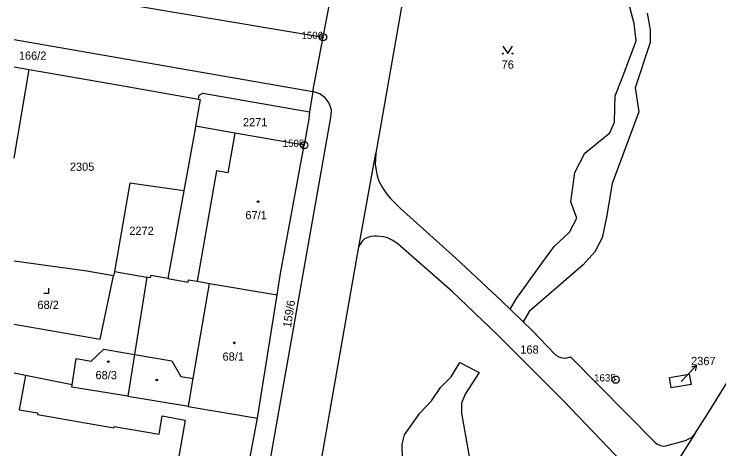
# Model space of a CAD drawing. Extents: x -866441 to -866144, y -1037389 to -1036968.
# Drawn here: x -866440.8 to -866295.1, y -1037160.7 to -1037070.9 of the extents above; entities that cross this region are included whole.
import ezdxf

# ---------------------------------------------------------------- set-up
doc = ezdxf.new("R2010")
doc.units = 0
for name, color, linetype in [('Hranice parcel', 7, 'Continuous'), ('Parcelní čísla', 7, 'Continuous'), ('Pop  PČ popisy', 7, 'Continuous'), ('Vnitřní kresba', 7, 'Continuous'), ('Značky bodu BP', 7, 'Continuous'), ('Značky budov', 7, 'Continuous'), ('Značky kultur', 7, 'Continuous')]:
    doc.layers.add(name, color=color, linetype=linetype)

msp = doc.modelspace()

# ---------------------------------------------------------------- linework, layer by layer
at = {"layer": 'Hranice parcel'}
for p, q in [((-866350.11, -1037008.35), (-866366.04, -1037099.65)), ((-866416.74, -1037068.97), (-866376.95, -1037075.67)), ((-866379.07, -1037086.89), (-866376.95, -1037075.67)), ((-866379.07, -1037086.89), (-866379.72, -1037091.09)), ((-866402.67, -1037088.49), (-866402.52, -1037087.66)), ((-866369.53, -1037118.99), (-866366.04, -1037099.65)), ((-866366.04, -1037099.65), (-866366.15, -1037102)), ((-866405.68, -1037107.4), (-866409.04, -1037125.54)), ((-866420.06, -1037124.1), (-866420.22, -1037124.95)), ((-866420.06, -1037124.1), (-866413.33, -1037125.28)), ((-866390.49, -1037154.39), (-866386.41, -1037128.93)), ((-866338.3, -1037131.85), (-866336.98, -1037129.68)), ((-866340, -1037130.19), (-866338.3, -1037131.85)), ((-866338.3, -1037131.85), (-866335.57, -1037134.5)), ((-866334.34, -1037132.32), (-866335.57, -1037134.5)), ((-866335.57, -1037134.5), (-866333.81, -1037136.22)), ((-866333.81, -1037136.22), (-866328.88, -1037141.28)), ((-866325.79, -1037141.71), (-866308.39, -1037159.36)), ((-866394.75, -1037177.03), (-866390.49, -1037154.39)), ((-866300.13, -1037157.61), (-866312.39, -1037176.98))]:
    msp.add_line(p, q, dxfattribs=at)
for points in [[(-866376.95, -1037075.67), (-866375.14, -1037066.22), (-866374.99, -1037066.24), (-866374.87, -1037065.62), (-866375.02, -1037065.59), (-866374.54, -1037063.06), (-866374.44, -1037063.08), (-866372.61, -1037053.54)], [(-866300.13, -1037157.61), (-866297.32, -1037153.2), (-866289.02, -1037139.82), (-866270.86, -1037110.87), (-866241.88, -1037065.54), (-866239.67, -1037062), (-866244.58, -1037059.28), (-866243.12, -1037056.62)], [(-866336.98, -1037129.68), (-866331.67, -1037122.27), (-866329.2, -1037118.89), (-866326.01, -1037115.95), (-866324.53, -1037113.03), (-866325.73, -1037109.68), (-866324.88, -1037103.62), (-866322.83, -1037099.61), (-866317.68, -1037095.43), (-866316.72, -1037093.21), (-866316.64, -1037090.36), (-866316.57, -1037087.76), (-866314.97, -1037083.76), (-866312.25, -1037076.44), (-866312.63, -1037072.83), (-866314.11, -1037067.33)], [(-866310, -1037070.73), (-866309.37, -1037074.15), (-866309.33, -1037076.74), (-866312.43, -1037086.11), (-866311.68, -1037091.11), (-866317.18, -1037105.91), (-866318.35, -1037112.87), (-866319.3, -1037117.13), (-866320.8, -1037120.02), (-866323.21, -1037122.72), (-866334.34, -1037132.32)], [(-866440.78, -1037076.16), (-866379.07, -1037086.89)], [(-866440.78, -1037081.77), (-866438.83, -1037082.11), (-866437.65, -1037082.32)], [(-866440.78, -1037100.69), (-866439.18, -1037091.3), (-866437.65, -1037082.32)], [(-866437.65, -1037082.32), (-866419.02, -1037085.56), (-866402.67, -1037088.49)], [(-866430.07, -1037388.86), (-866412.87, -1037304.8), (-866375.25, -1037091.87), (-866375.18, -1037090.66), (-866375.67, -1037089.29), (-866376.51, -1037088.18), (-866377.58, -1037087.37), (-866379.07, -1037086.89)], [(-866402.52, -1037087.66), (-866401.75, -1037087.22), (-866379.72, -1037091.09)], [(-866402.67, -1037088.49), (-866402.3, -1037088.56), (-866403.28, -1037094.08)], [(-866379.72, -1037091.09), (-866379.88, -1037092.56), (-866380.82, -1037097.97)], [(-866403.28, -1037094.08), (-866403.37, -1037094.6), (-866405.68, -1037107.4)], [(-866380.82, -1037097.97), (-866395.17, -1037095.52), (-866403.28, -1037094.08)], [(-866386.41, -1037128.93), (-866385.72, -1037124.52), (-866380.82, -1037097.97)], [(-866366.15, -1037102), (-866366, -1037103.14), (-866365.99, -1037103.18), (-866365.74, -1037104.3), (-866365.39, -1037105.4), (-866364.8, -1037106.51), (-866364.48, -1037107.04), (-866363.76, -1037108.08), (-866362.96, -1037109.05)], [(-866405.68, -1037107.4), (-866416.87, -1037105.86), (-866420.06, -1037124.1)], [(-866362.96, -1037109.05), (-866360.97, -1037111.04), (-866349.52, -1037121.34), (-866340, -1037130.19)], [(-866362.5, -1037117.65), (-866363.24, -1037117.3), (-866363.63, -1037117.15), (-866364.42, -1037116.94), (-866365.23, -1037116.83), (-866365.93, -1037116.77), (-866366.33, -1037116.78), (-866367.04, -1037116.88), (-866367.71, -1037117.07), (-866368.36, -1037117.36), (-866368.8, -1037117.76), (-866368.96, -1037117.95), (-866369.29, -1037118.45), (-866369.53, -1037118.99)], [(-866313.18, -1037165.84), (-866315.06, -1037163.56), (-866327.2, -1037150.88), (-866340.96, -1037137.11), (-866350.28, -1037128.19), (-866361.44, -1037118.43), (-866362.5, -1037117.65)], [(-866384.32, -1037301.69), (-866385.21, -1037304.38), (-866385.77, -1037305.47), (-866386.48, -1037306.77), (-866387.33, -1037307.83), (-866388.02, -1037308.57), (-866388.93, -1037309.23), (-866390.08, -1037309.63), (-866391.08, -1037309.72), (-866392.26, -1037309.62), (-866393.53, -1037309.3), (-866394.53, -1037308.94), (-866395.58, -1037308.42), (-866396.69, -1037307.68), (-866398.06, -1037306.42), (-866398.71, -1037305.64), (-866399.33, -1037304.73), (-866399.73, -1037303.92), (-866400.33, -1037302.58), (-866400.68, -1037301.33), (-866400.93, -1037299.71), (-866400.97, -1037298.54), (-866400.35, -1037294.48), (-866369.53, -1037118.99)], [(-866420.22, -1037124.95), (-866425.75, -1037124.04), (-866440.78, -1037121.94)], [(-866440.78, -1037134.94), (-866423.02, -1037138.05), (-866420.22, -1037124.95)], [(-866413.33, -1037125.28), (-866415.9, -1037141.22), (-866417.29, -1037149.84)], [(-866409.04, -1037125.54), (-866412.55, -1037124.92), (-866412.64, -1037125.4), (-866413.33, -1037125.28)], [(-866409.04, -1037125.54), (-866404.8, -1037126.28), (-866404.72, -1037125.79), (-866402.93, -1037126.11), (-866400.41, -1037126.54), (-866386.41, -1037128.93)], [(-866328.88, -1037141.28), (-866328.46, -1037141.58), (-866328.36, -1037141.63), (-866327.88, -1037141.82), (-866327.37, -1037141.92), (-866326.87, -1037141.96), (-866326.76, -1037141.96), (-866326.26, -1037141.88), (-866325.79, -1037141.71)], [(-866360.55, -1037163.1), (-866360.62, -1037159.73), (-866360.1, -1037157.81), (-866356.94, -1037153.32), (-866354.51, -1037150.81), (-866352.69, -1037148.03), (-866350.49, -1037145.82), (-866348.66, -1037142.87), (-866344.69, -1037144.95), (-866347.56, -1037149.43), (-866348.32, -1037151.28), (-866348.34, -1037153.32), (-866345.89, -1037167.01)], [(-866428.81, -1037147.47), (-866438.45, -1037145.56), (-866440.78, -1037145.1)], [(-866301.27, -1037145.27), (-866300.89, -1037147.42), (-866304.99, -1037148.15), (-866305.37, -1037146), (-866301.27, -1037145.27)], [(-866417.29, -1037149.84), (-866428.88, -1037147.95), (-866428.81, -1037147.47)], [(-866417.29, -1037149.84), (-866404.77, -1037151.88), (-866404.79, -1037151.99), (-866390.49, -1037154.39)], [(-866306.14, -1037160.13), (-866302.05, -1037159.02), (-866300.81, -1037158.39), (-866300.13, -1037157.61)], [(-866308.39, -1037159.36), (-866307.97, -1037159.69), (-866307.69, -1037159.85), (-866307.19, -1037160.04), (-866306.67, -1037160.14), (-866306.14, -1037160.13)]]:
    msp.add_lwpolyline(points, dxfattribs=at)
at = {"layer": 'Pop  PČ popisy'}
for p, q in [((-866301.83, -1037145.67), (-866299.74, -1037143.51)), ((-866299.74, -1037143.51), (-866300.8, -1037143.88)), ((-866299.74, -1037143.51), (-866300.08, -1037144.58)), ((-866302.93, -1037146.79), (-866301.83, -1037145.67))]:
    msp.add_line(p, q, dxfattribs=at)
at = {"layer": 'Vnitřní kresba'}
for p, q in [((-866395.17, -1037095.52), (-866396.59, -1037103.66)), ((-866398.93, -1037103.28), (-866402.93, -1037126.11)), ((-866396.59, -1037103.66), (-866398.93, -1037103.28)), ((-866403.8, -1037146.21), (-866400.41, -1037126.54)), ((-866424.84, -1037142.6), (-866422.27, -1037140.12)), ((-866422.27, -1037140.12), (-866415.9, -1037141.22)), ((-866415.9, -1037141.22), (-866408.21, -1037142.54)), ((-866428.81, -1037147.47), (-866427.96, -1037142.09)), ((-866427.96, -1037142.09), (-866424.84, -1037142.6)), ((-866408.21, -1037142.54), (-866406.31, -1037145.77)), ((-866438.45, -1037145.56), (-866439.73, -1037152.66)), ((-866406.31, -1037145.77), (-866403.8, -1037146.21)), ((-866404.77, -1037151.88), (-866403.8, -1037146.21)), ((-866439.73, -1037152.66), (-866435.92, -1037153.27)), ((-866435.92, -1037153.27), (-866435.98, -1037153.61)), ((-866435.98, -1037153.61), (-866420.19, -1037156.36)), ((-866410.84, -1037157.67), (-866410.19, -1037153.93)), ((-866410.19, -1037153.93), (-866405.46, -1037154.78)), ((-866405.46, -1037154.78), (-866408.2, -1037170.57)), ((-866420.19, -1037156.36), (-866420.13, -1037156.1)), ((-866420.13, -1037156.1), (-866410.84, -1037157.67))]:
    msp.add_line(p, q, dxfattribs=at)
at = {"layer": 'Značky bodu BP'}
for centre, radius in [((-866376.95, -1037075.67), 0.75), ((-866376.95, -1037075.67), 0.03), ((-866380.82, -1037097.97), 0.75), ((-866380.82, -1037097.97), 0.03), ((-866316.48, -1037146.43), 0.75), ((-866316.48, -1037146.43), 0.03)]:
    msp.add_circle(centre, radius, dxfattribs=at)
at = {"layer": 'Značky budov'}
for centre in [(-866390.36, -1037109.66), (-866395.27, -1037138.82), (-866421.3, -1037142.71), (-866411.3, -1037146.51)]:
    msp.add_circle(centre, 0.175, dxfattribs=at)
at = {"layer": 'Značky kultur'}
for p, q in [((-866433.61, -1037128.53), (-866433.61, -1037127.53)), ((-866434.61, -1037128.53), (-866433.61, -1037128.53))]:
    msp.add_line(p, q, dxfattribs=at)
msp.add_lwpolyline([(-866339.78, -1037077.54), (-866338.78, -1037079.04), (-866337.78, -1037077.54)], dxfattribs=at)
for centre in [(-866339.78, -1037079.04), (-866337.78, -1037079.04)]:
    msp.add_circle(centre, 0.1, dxfattribs=at)

# ---------------------------------------------------------------- texts
at = {"layer": 'Parcelní čísla'}
for s, p in [('166/2', (-866439.8, -1037080.33)), ('76', (-866340.04, -1037082.17)), ('2271', (-866393.5, -1037094.08)), ('2305', (-866429.26, -1037103.28)), ('67/1', (-866392.99, -1037113.29)), ('2272', (-866416.98, -1037116.52)), ('68/2', (-866435.96, -1037131.82)), ('168', (-866336.18, -1037141.07)), ('68/1', (-866397.71, -1037142.51)), ('2367', (-866300.89, -1037143.42)), ('68/3', (-866423.96, -1037146.34))]:
    msp.add_text(s, height=1.7, dxfattribs=at).set_placement(p)
msp.add_text('159/6', height=1.7, rotation=81, dxfattribs=at).set_placement((-866383.58, -1037135.77))
at = {"layer": 'Značky bodu BP'}
for s, p in [('1506', (-866381.4, -1037076.05)), ('1505', (-866385.27, -1037098.34)), ('1635', (-866320.93, -1037146.81))]:
    msp.add_text(s, height=1.5, dxfattribs=at).set_placement(p)

doc.saveas('drawing.dxf')
